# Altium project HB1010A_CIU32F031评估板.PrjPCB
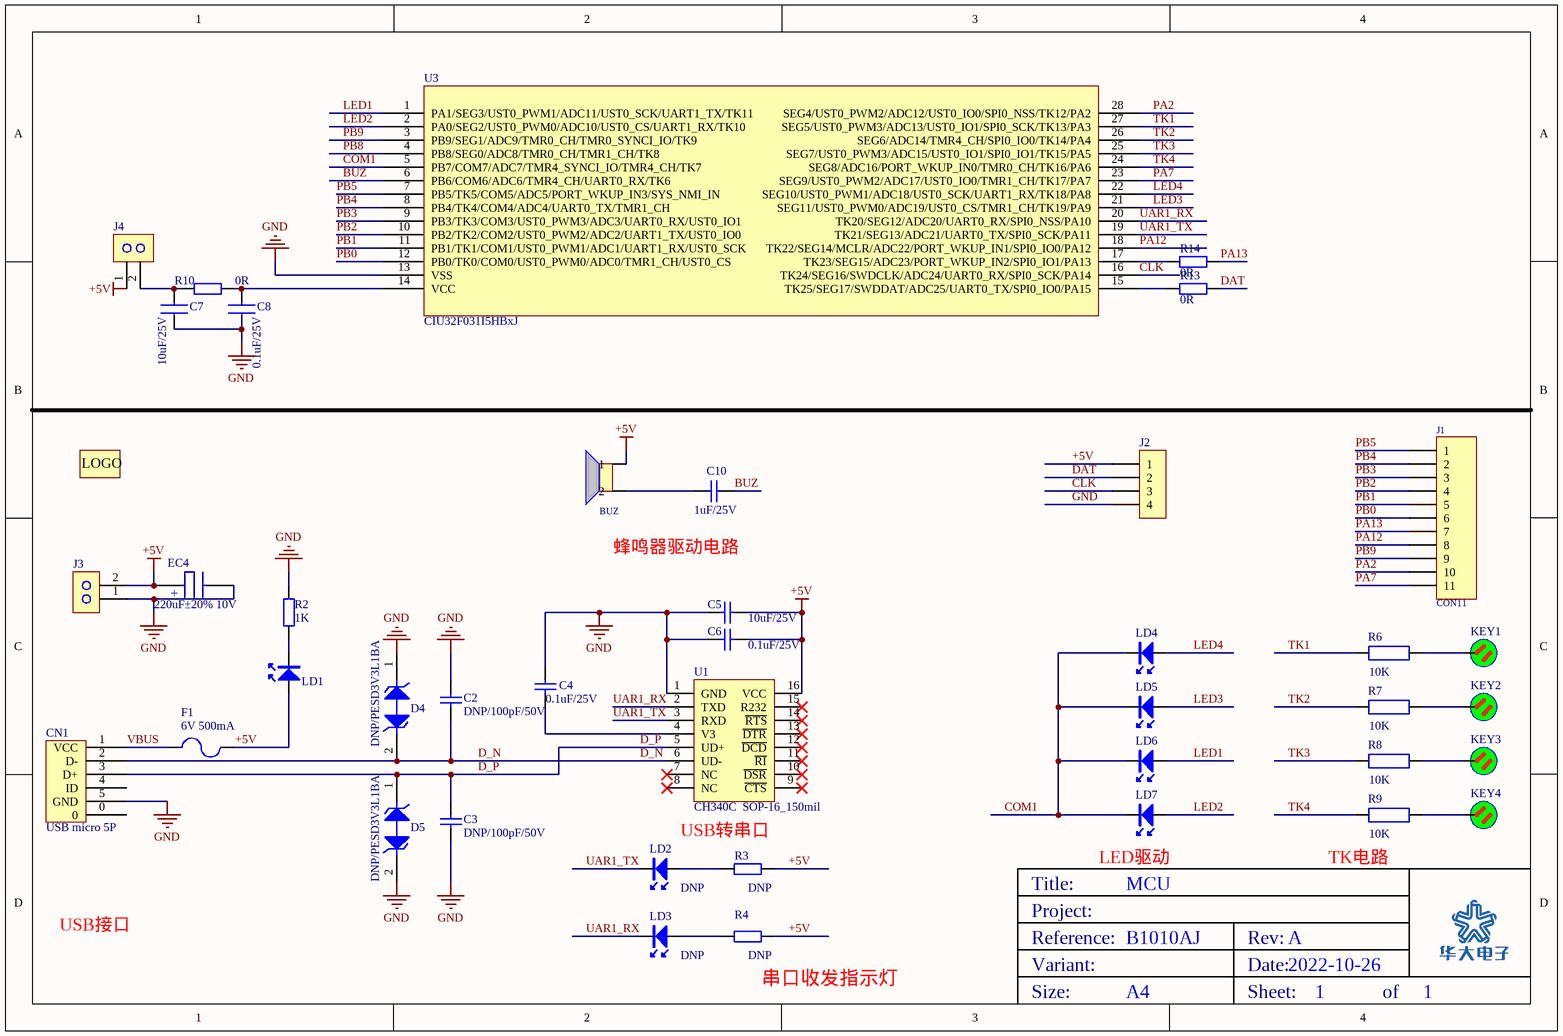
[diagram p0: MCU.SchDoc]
Board_Assembly_Revision: 01; Board_PCB_Revision: A; Board_Reference: B1010AJ
1 sheet, 42 parts. Net scope: global (net labels, ports and power ports of the same name join across sheets).
Board file: HB1010AJ.PcbDoc

## Sheet MCU.SchDoc: MCU
size A4; Date: 2022-10-26; SheetNumber: 1; SheetTotal: 1

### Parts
BUZ  BUZZ  [BUZZ-90X32-SMD]  (value not drawn)
C2  DNP/100pF/50V  [0603C]
C3  DNP/100pF/50V  [0603C]
C4  0.1uF/25V  [0603C]
C5  10uF/25V  [0603C]
C6  0.1uF/25V  [0603C]
C7  10uF/25V  [0603C]
C8  0.1uF/25V  [0603C]
C10  value 1uF/25V  [0603c]  (hidden comment: 0603-25V-2.2μF±10% X5R)
CN1  USB micro 5P  [MicroUSB - 7P2]
D4  DNP/PESD3V3L1BA  [SOD-323]
D5  DNP/PESD3V3L1BA  [SOD-323]
EC4  value 220uF±20% 10V  [ECAP-D6.3]  (hidden comment: 220uF±20% 10V SMD,6.3x5.4mm)
F1  6V 500mA  [SF1206]
J1  CON11  [sip11]
J2  CON4  [SIP4]  (value not drawn)
J3  (no value)  [SIP2]
J4  (no value)  [SIP2]
KEY1  (no value)  [弹簧6mm]
KEY2  (no value)  [弹簧6mm]
KEY3  (no value)  [弹簧6mm]
KEY4  (no value)  [弹簧6mm]
LD1  17-21SURC/S530-A3/TR8  发光二极管/0805 红灯 (Iv=61mcd(Typ) @IF=20mA)  [D0805]  (value not drawn)
LD2  DNP  [D0805]
LD3  DNP  [D0805]
LD4  17-21SURC/S530-A3/TR8  发光二极管/0805 红灯 (Iv=61mcd(Typ) @IF=20mA)  [D0805]  (value not drawn)
LD5  17-21SURC/S530-A3/TR8  发光二极管/0805 红灯 (Iv=61mcd(Typ) @IF=20mA)  [D0805]  (value not drawn)
LD6  17-21SURC/S530-A3/TR8  发光二极管/0805 红灯 (Iv=61mcd(Typ) @IF=20mA)  [D0805]  (value not drawn)
LD7  17-21SURC/S530-A3/TR8  发光二极管/0805 红灯 (Iv=61mcd(Typ) @IF=20mA)  [D0805]  (value not drawn)
LOGO1  LOGO  [LOGO_HED_10mm]  (value not drawn)
R2  1K  [0603]
R3  DNP  [0603]
R4  DNP  [0603]
R6  value 10K  [0603]  (hidden comment: 10KΩ(1002) ±1% 0603WAF1002T5E)
R7  value 10K  [0603]  (hidden comment: 10KΩ(1002) ±1% 0603WAF1002T5E)
R8  value 10K  [0603]  (hidden comment: 10KΩ(1002) ±1% 0603WAF1002T5E)
R9  value 10K  [0603]  (hidden comment: 10KΩ(1002) ±1% 0603WAF1002T5E)
R10  value 0R  [R0603]  (hidden comment: 0603WAF0000T5E 0R 1% 0603)
R13  value 0R  [R0603]  (hidden comment: 0603WAF0000T5E 0R 1% 0603)
R14  value 0R  [R0603]  (hidden comment: 0603WAF0000T5E 0R 1% 0603)
U1  CH340C  SOP-16_150mil  [SO-16]
U3  CIU32F031I5HBxJ  [SSOP28]

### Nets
+5V: BUZ.1 C5.2 C6.2 EC4.1 F1.2 J2.1 J3.2 J4.1 LD1.1(A) R3.1 R4.1 U1.16(VCC)
GND: C2.1 C3.2 C4.1 C5.1 C6.1 C7.2 C8.2 CN1.5(GND) D4.1 D5.2 EC4.2 J2.4 J3.1 R2.2 U1.1(GND) U3.13(VSS)
BUZ: C10.1 U3.6(PB6/COM6/ADC6/TMR4_CH/UART0_RX/TK6)
CLK: J2.3 U3.16(TK24/SEG16/SWDCLK/ADC24/UART0_RX/SPI0_SCK/PA14)
COM1: LD4.2(K) LD5.2(K) LD6.2(K) LD7.2(K) U3.5(PB7/COM7/ADC7/TMR4_SYNCI_IO/TMR4_CH/TK7)
D_N: C2.2 CN1.2(D-) D4.2 U1.6(UD-)
D_P: C3.1 CN1.3(D+) D5.1 U1.5(UD+)
DAT: J2.2 R13.1
LED1: LD6.1(A) U3.1(PA1/SEG3/UST0_PWM1/ADC11/UST0_SCK/UART1_TX/TK11)
LED2: LD7.1(A) U3.2(PA0/SEG2/UST0_PWM0/ADC10/UST0_CS/UART1_RX/TK10)
LED3: LD5.1(A) U3.21(SEG11/UST0_PWM0/ADC19/UST0_CS/TMR1_CH/TK19/PA9)
LED4: LD4.1(A) U3.22(SEG10/UST0_PWM1/ADC18/UST0_SCK/UART1_RX/TK18/PA8)
PA2: J1.10 U3.28(SEG4/UST0_PWM2/ADC12/UST0_IO0/SPI0_NSS/TK12/PA2)
PA7: J1.11 U3.23(SEG9/UST0_PWM2/ADC17/UST0_IO0/TMR1_CH/TK17/PA7)
PA12: J1.8 U3.18(TK22/SEG14/MCLR/ADC22/PORT_WKUP_IN1/SPI0_IO0/PA12)
PA13: J1.7 R14.1
PB0: J1.6 U3.12(PB0/TK0/COM0/UST0_PWM0/ADC0/TMR1_CH/UST0_CS)
PB1: J1.5 U3.11(PB1/TK1/COM1/UST0_PWM1/ADC1/UART1_RX/UST0_SCK)
PB2: J1.4 U3.10(PB2/TK2/COM2/UST0_PWM2/ADC2/UART1_TX/UST0_IO0)
PB3: J1.3 U3.9(PB3/TK3/COM3/UST0_PWM3/ADC3/UART0_RX/UST0_IO1)
PB4: J1.2 U3.8(PB4/TK4/COM4/ADC4/UART0_TX/TMR1_CH)
PB5: J1.1 U3.7(PB5/TK5/COM5/ADC5/PORT_WKUP_IN3/SYS_NMI_IN)
PB8: U3.4(PB8/SEG0/ADC8/TMR0_CH/TMR1_CH/TK8)
PB9: J1.9 U3.3(PB9/SEG1/ADC9/TMR0_CH/TMR0_SYNCI_IO/TK9)
TK1: R6.2 U3.27(SEG5/UST0_PWM3/ADC13/UST0_IO1/SPI0_SCK/TK13/PA3)
TK2: R7.2 U3.26(SEG6/ADC14/TMR4_CH/SPI0_IO0/TK14/PA4)
TK3: R8.2 U3.25(SEG7/UST0_PWM3/ADC15/UST0_IO1/SPI0_IO1/TK15/PA5)
TK4: R9.2 U3.24(SEG8/ADC16/PORT_WKUP_IN0/TMR0_CH/TK16/PA6)
UAR1_RX: LD3.2(K) U1.2(TXD) U3.20(TK20/SEG12/ADC20/UART0_RX/SPI0_NSS/PA10)
UAR1_TX: LD2.2(K) U1.3(RXD) U3.19(TK21/SEG13/ADC21/UART0_TX/SPI0_SCK/PA11)
VBUS: CN1.1(VCC) F1.1
NetBUZ_2: BUZ.2 C10.2
NetC4_2: C4.2 U1.4(V3)
NetC7_1: C7.1 J4.2 R10.1
NetC8_1: C8.1 R10.2 U3.14(VCC)
NetKEY1_1: KEY1.1 R6.1
NetKEY2_1: KEY2.1 R7.1
NetKEY3_1: KEY3.1 R8.1
NetKEY4_1: KEY4.1 R9.1
NetLD1_2: LD1.2(K) R2.1
NetLD2_1: LD2.1(A) R3.2
NetLD3_1: LD3.1(A) R4.2
NetR13_2: R13.2 U3.15(TK25/SEG17/SWDDAT/ADC25/UART0_TX/SPI0_IO0/PA15)
NetR14_2: R14.2 U3.17(TK23/SEG15/ADC23/PORT_WKUP_IN2/SPI0_IO1/PA13)

Not connected (* = marked no-connect by the designer): CN1 0 4(ID); U1 7(NC)* 8(NC)* 9(~{CTS})* 10(~{DSR})* 11(~{RI})* 12(~{DCD})* 13(~{DTR})* 14(~{RTS})* 15(R232)*

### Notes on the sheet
- 蜂鸣器驱动电路
- USB转串口
- (near LD7) LED驱动
- (near R9) TK电路
- USB接口
- 串口收发指示灯

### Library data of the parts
BUZ = BUZZ: 贴片蜂鸣器
C2-C6 C10 = cap 0603: 贴片电容
C7 C8 = CAP
D4 D5 = TVS
EC4 = E_CAP01
F1 = Fuse_SMD: 贴片保险丝
J1 = CON11: 2.54mm 1*11P公插针/2.54mm 1*11P 直 排针
J2 = CON4: 2.54mm 1*4P公插针/2.54mm 1*4P 直 排针
J3 J4 = CON2: 2.54mm 1*2P?公插针/2.54mm 1*2P 直 排针
KEY1-KEY4 = CHUMO-PAD: 直筒内绕偏心类 小家电触摸弹簧 按键弹簧 SUS304 开关按键 F12-20-内5-0.5直筒内绕偏心
LD1 LD4-LD7 = LED: 贴片LED
LD2 LD3 = LED
R2 = res 0603: 贴片电阻
R3 R4 = res 0603: 贴片电阻; Value: 1K
R6-R9 = RES1: 贴片电阻
R10 R13 R14 = Res2: Resistor
U1 = CH340C: IC
U3 = CIU32F011I3FBxJ

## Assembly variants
None: not fitted C2 C3 D4 D5 LD2 LD3 LOGO1 R3 R4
